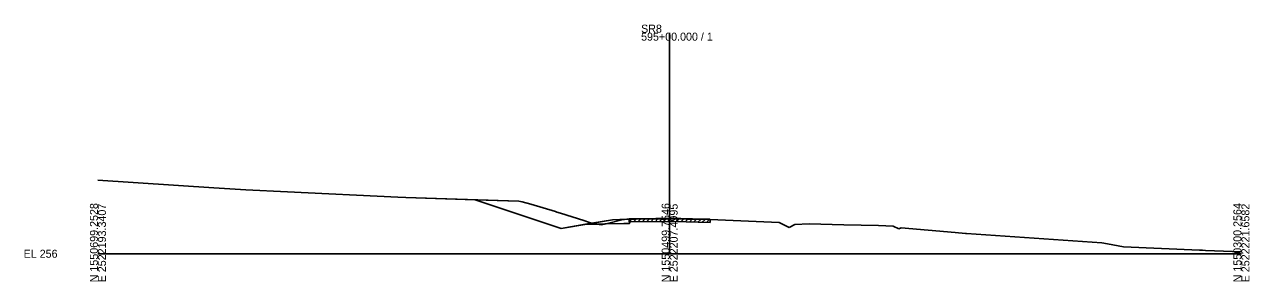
# Model space of a CAD drawing. Extents: x -26 to 2803, y -10 to 19537.
# Drawn here: x -25.7 to 402.8, y 4990.3 to 5080.1 of the extents above; entities that cross this region are included whole.
import ezdxf

# ---------------------------------------------------------------- set-up
doc = ezdxf.new("R2010")
doc.units = 0
for name, color, linetype in [('1', 7, 'Continuous'), ('Draft_XS_Grid', 7, 'Continuous'), ('Draft_XS_Text', 7, 'Continuous'), ('DTM_P_SUBGRADE_1', 7, 'Continuous'), ('DTM_X_GROUND', 7, 'Continuous'), ('SLOPE_STAKES_FILL', 7, 'Continuous'), ('XS_P_SHOULDER', 7, 'Continuous')]:
    doc.layers.add(name, color=color, linetype=linetype)

msp = doc.modelspace()

# ---------------------------------------------------------------- linework, layer by layer
at = {"layer": '1'}
for p, q in [((200, 5000), (200, 5077.24)), ((0, 5000), (200, 5000)), ((200, 5000), (400, 5000))]:
    msp.add_line(p, q, dxfattribs=at)
at = {"layer": 'Draft_XS_Grid'}
for p, q in [((185.89, 5011.15), (186.89, 5012.15)), ((185.89, 5011.15), (185.89, 5012.15)), ((185.89, 5011.15), (186.44, 5011.15)), ((186.44, 5011.15), (200, 5011.24)), ((187.39, 5011.16), (188.39, 5012.16)), ((188.89, 5011.17), (189.89, 5012.17)), ((190.39, 5011.18), (191.39, 5012.18)), ((191.89, 5011.19), (192.89, 5012.19)), ((193.39, 5011.2), (194.39, 5012.2)), ((194.89, 5011.2), (195.89, 5012.21)), ((196.39, 5011.21), (197.39, 5012.22)), ((197.89, 5011.22), (198.89, 5012.23)), ((199.39, 5011.23), (200.38, 5012.23)), ((200, 5011.24), (205.82, 5011.1)), ((200.89, 5011.22), (201.87, 5012.19)), ((202.39, 5011.18), (203.37, 5012.16)), ((203.89, 5011.15), (204.87, 5012.13)), ((205.39, 5011.11), (206.37, 5012.09)), ((205.82, 5011.1), (214.18, 5010.91)), ((206.89, 5011.08), (207.87, 5012.06)), ((208.39, 5011.04), (209.37, 5012.02)), ((209.89, 5011.01), (210.87, 5011.99)), ((211.39, 5010.97), (212.37, 5011.95)), ((212.89, 5010.94), (213.87, 5011.92)), ((214.18, 5011.91), (214.18, 5010.91))]:
    msp.add_line(p, q, dxfattribs=at)
at = {"layer": 'Draft_XS_Text'}
for p, q in [((238.29, 5010.93), (241.78, 5009.2)), ((241.78, 5009.2), (243.8, 5010.2)), ((243.8, 5010.2), (248.85, 5010.4)), ((248.85, 5010.4), (260.97, 5010.13)), ((260.97, 5010.13), (273.09, 5009.85)), ((273.09, 5009.85), (278.13, 5009.65)), ((278.13, 5009.65), (280.15, 5008.65)), ((280.15, 5008.65), (280.93, 5009.04))]:
    msp.add_line(p, q, dxfattribs=at)
for points in [[(0, 5025.75), (40.49, 5023.02), (51.73, 5022.27), (66.27, 5021.58), (104.91, 5019.76), (107.75, 5019.66), (147.22, 5018.34), (148.43, 5018.09), (151.41, 5017.26), (160.06, 5014.71), (160.58, 5014.55), (161.85, 5014.15), (169.92, 5011.57), (171.93, 5010.93), (173.07, 5010.56), (176.19, 5010.12), (177.68, 5010.42), (178.75, 5010.65), (183.22, 5011.84), (185.89, 5012.15), (186.44, 5012.15), (200, 5012.24), (205.82, 5012.1), (214.18, 5011.91), (238.29, 5010.93)], [(280.93, 5009.04), (299.84, 5007.41), (303.52, 5007.08), (303.85, 5007.05), (351.17, 5003.8), (353.22, 5003.42), (358.77, 5002.41), (385.33, 5001.28), (386.08, 5001.24), (386.45, 5001.22), (387.47, 5001.18), (400, 5000.65)]]:
    msp.add_lwpolyline(points, dxfattribs=at)
at = {"layer": 'DTM_P_SUBGRADE_1'}
for p, q in [((184, 5010.55), (170.59, 5010.28)), ((186, 5010.59), (184, 5010.55)), ((186, 5010.59), (186, 5012.09))]:
    msp.add_line(p, q, dxfattribs=at)
at = {"layer": 'DTM_X_GROUND'}
for p, q in [((162, 5008.85), (132, 5018.85)), ((180, 5011.85), (162, 5008.85)), ((186, 5012.09), (180, 5011.85)), ((188, 5012.13), (186, 5012.09)), ((188, 5012.13), (200, 5012.37)), ((200, 5012.37), (212, 5012.13)), ((212, 5012.13), (214, 5012.09)), ((214, 5012.09), (214, 5011.91))]:
    msp.add_line(p, q, dxfattribs=at)
at = {"layer": 'SLOPE_STAKES_FILL'}
for p, q in [((132, 5018.85), (162, 5008.85)), ((162, 5008.85), (180, 5011.85)), ((180, 5011.85), (186, 5012.09)), ((186, 5012.09), (188, 5012.13)), ((188, 5012.13), (200, 5012.37)), ((200, 5012.37), (212, 5012.13)), ((212, 5012.13), (214, 5012.09)), ((214, 5012.09), (214, 5011.91)), ((238.29, 5010.93), (241.78, 5009.2)), ((241.78, 5009.2), (243.8, 5010.2)), ((243.8, 5010.2), (248.85, 5010.4)), ((248.85, 5010.4), (260.97, 5010.13)), ((260.97, 5010.13), (273.09, 5009.85)), ((273.09, 5009.85), (278.13, 5009.65)), ((278.13, 5009.65), (280.15, 5008.65)), ((280.15, 5008.65), (280.93, 5009.04))]:
    msp.add_line(p, q, dxfattribs=at)
for points in [[(0, 5025.75), (40.49, 5023.02), (51.73, 5022.27), (66.27, 5021.58), (104.91, 5019.76), (107.75, 5019.66), (132, 5018.85)], [(214, 5011.91), (214.18, 5011.91), (238.29, 5010.93)], [(280.93, 5009.04), (299.84, 5007.41), (303.52, 5007.08), (303.85, 5007.05), (351.17, 5003.8), (353.22, 5003.42), (358.77, 5002.41), (385.33, 5001.28), (386.08, 5001.24), (386.45, 5001.22), (387.47, 5001.18), (400, 5000.65)]]:
    msp.add_lwpolyline(points, dxfattribs=at)
at = {"layer": 'XS_P_SHOULDER'}
for points in [[(171.93, 5010.93), (172.79, 5010.65), (170.59, 5010.28), (162, 5008.85), (132, 5018.85), (147.22, 5018.34), (148.43, 5018.09), (151.41, 5017.26), (160.06, 5014.71), (160.58, 5014.55), (161.85, 5014.15), (169.92, 5011.57)], [(172.79, 5010.65), (173.07, 5010.56), (174.47, 5010.36), (170.59, 5010.28)], [(178.75, 5010.65), (183.22, 5011.84), (185.08, 5012.05), (180, 5011.85), (172.79, 5010.65), (173.07, 5010.56), (174.47, 5010.36), (177.7, 5010.42)], [(177.7, 5010.42), (174.47, 5010.36), (176.19, 5010.12), (177.68, 5010.42)], [(184, 5010.55), (177.7, 5010.42), (178.75, 5010.65), (183.22, 5011.84), (185.08, 5012.05), (185.89, 5012.09), (185.89, 5011.15), (186, 5011.15), (186, 5010.59)], [(185.89, 5012.09), (185.89, 5012.15), (185.08, 5012.05)], [(186, 5012.09), (185.89, 5012.09), (185.89, 5012.15), (186.44, 5012.15), (190.3, 5012.18), (188, 5012.13)], [(186, 5012.09), (185.89, 5012.09), (185.89, 5011.15), (186, 5011.15)], [(212, 5012.13), (214, 5012.09), (214, 5011.91), (205.82, 5012.1), (200, 5012.24), (190.3, 5012.18), (200, 5012.37)]]:
    msp.add_lwpolyline(points, close=True, dxfattribs=at)

# ---------------------------------------------------------------- texts
at = {"layer": '1'}
for s, p in [('SR8', (190, 5077.24)), ('595+00.000 / 1', (190, 5074.44)), ('EL 256', (-26, 4998.6))]:
    msp.add_text(s, height=2.8, dxfattribs=at).set_placement(p)
for s, p in [('N 1550699.2528', (0, 4990)), ('E 2522193.3407', (2.8, 4990)), ('N 1550499.7546', (200, 4990)), ('E 2522207.4995', (202.8, 4990)), ('N 1550300.2564', (400, 4990)), ('E 2522221.6582', (402.8, 4990))]:
    msp.add_text(s, height=2.8, rotation=90, dxfattribs=at).set_placement(p)

doc.saveas('drawing.dxf')
